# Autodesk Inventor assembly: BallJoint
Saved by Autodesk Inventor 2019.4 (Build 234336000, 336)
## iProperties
Created: 2020-04
Part Number: BallJoint
Document SubType Name: Assembly
Designer: Administrator
Title: BallJoint v14
Author: Administrator
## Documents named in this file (3)
- c:\worker\convert-fusion-r03\tmp\job-1\48\output\files\ccae6ef3-9f0e-42ff-b199-3a2c6474057a\BallJoint v14_5.iam
- c:\worker\convert-fusion-r03\tmp\job-1\48\output\files\ccae6ef3-9f0e-42ff-b199-3a2c6474057a\Component1_1.ipt
- c:\worker\convert-fusion-r03\tmp\job-1\48\output\files\ccae6ef3-9f0e-42ff-b199-3a2c6474057a\Component2_1.ipt
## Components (2 placed, 2 different names)
1. Component1:1
2. Component2:1
